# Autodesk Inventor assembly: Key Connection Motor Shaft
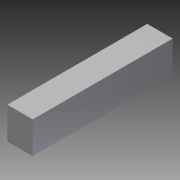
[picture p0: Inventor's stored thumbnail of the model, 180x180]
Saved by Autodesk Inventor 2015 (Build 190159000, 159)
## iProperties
Created: 2007-02
Part Number: Key Connection Motor Shaft
Document SubType Name: Assembly
Designer: Autodesk, Inc.
Mass: 13.8362 g
Surface Area: 10.9879 cm^2
Volume: 1.76033 cm^3
Density: 7.86 g/cm^3
ClientObjectVersion: 1
Author: Autodesk, Inc.
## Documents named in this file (2)
- C:\Users\Public\Documents\Autodesk\Inventor 2015\Samples\Models\Assemblies\Blower\Blower\Design Accelerator\Key Connection3.iam
- C:\Users\Public\Documents\Autodesk\Inventor 2015\Samples\Standard Parts\en-US\USAS B17.1(1)\USAS B17.1 - 5_16 x 1_4 x 1 3_8.ipt
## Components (1 placed, 1 different names)
1. Rectangular 5/16 x 1/4 x 1 3/8:1
